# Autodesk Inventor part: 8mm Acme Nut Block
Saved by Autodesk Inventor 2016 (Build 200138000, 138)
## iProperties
Created: 2015-11
Part Number: 8mm Acme Nut Block
Material: Generic
Document SubType Name: Modeling
Designer: John
Density: 1 g/cm^3
Appearance: Default
Author: John
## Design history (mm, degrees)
feature "SOLID1"
body "Solid1"
